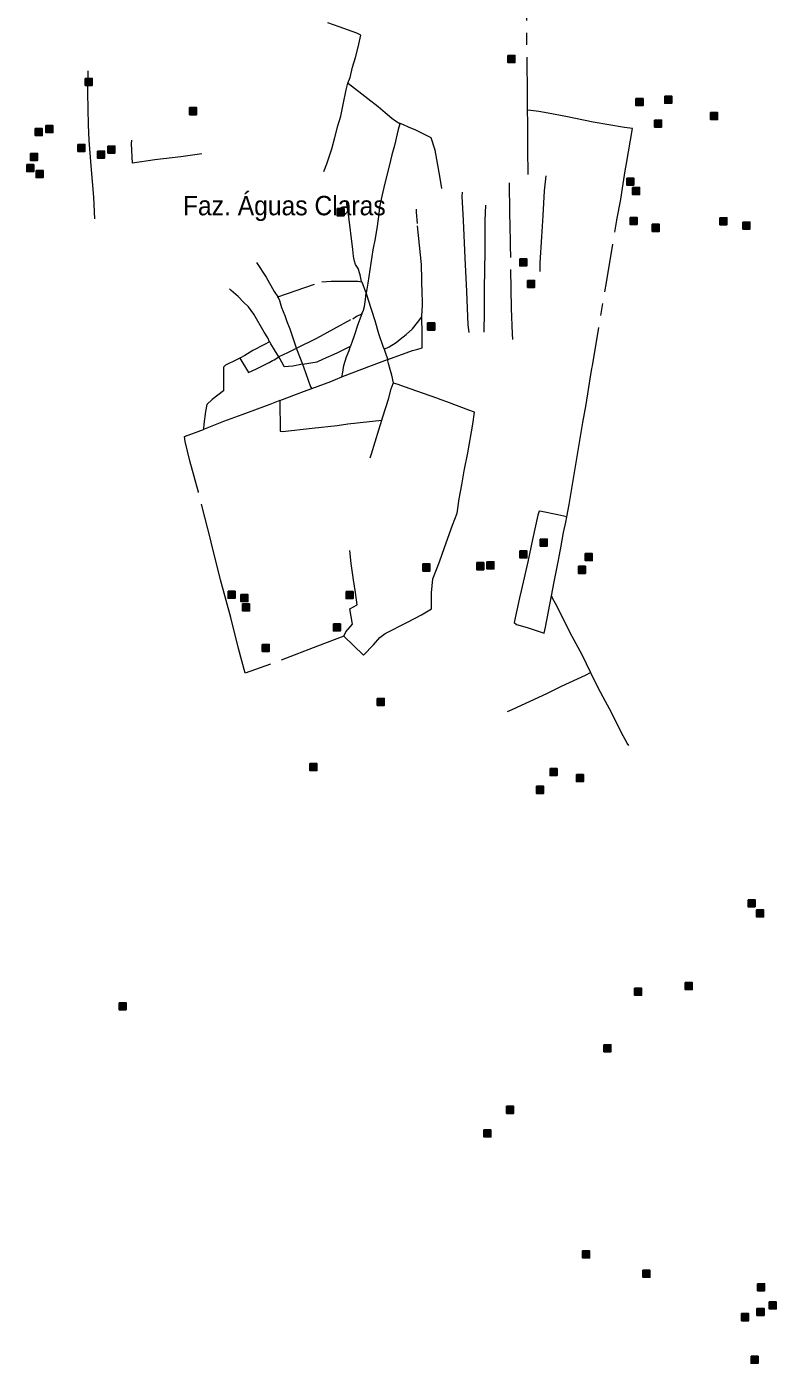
# Model space of a CAD drawing. Extents: x 393.5 to 446.9, y 8064.8 to 8120.4.
# Drawn here: x 432.73 to 438.91, y 8065.16 to 8076.18 of the extents above; entities that cross this region are included whole.
import ezdxf

# ---------------------------------------------------------------- set-up
doc = ezdxf.new("R2010")
doc.units = 0
doc.header["$LTSCALE"] = 0.064
doc.linetypes.add('DOT_DASHED', pattern=[7.7, 5, -1.2, 0.3, -1.2])
doc.layers.add('2', color=7, linetype='Continuous', lineweight=25)
doc.layers.add('22', color=7, linetype='DOT_DASHED', lineweight=13)
doc.layers.add('61', color=7, linetype='Continuous')

msp = doc.modelspace()

# ---------------------------------------------------------------- hatches: boundary and pattern name
at = {"layer": '2'}
for points in [[(436.7008, 8075.9394), (436.7588, 8075.9394), (436.7588, 8075.8814), (436.7008, 8075.8814)], [(433.2153, 8075.7507), (433.2733, 8075.7507), (433.2733, 8075.6927), (433.2153, 8075.6927)], [(434.0766, 8075.5093), (434.1346, 8075.5093), (434.1346, 8075.4513), (434.0766, 8075.4513)], [(437.757, 8075.584), (437.815, 8075.584), (437.815, 8075.526), (437.757, 8075.526)], [(437.9944, 8075.6043), (438.0524, 8075.6043), (438.0524, 8075.5463), (437.9944, 8075.5463)], [(437.9107, 8075.4072), (437.9687, 8075.4072), (437.9687, 8075.3492), (437.9107, 8075.3492)], [(438.3714, 8075.4688), (438.4294, 8075.4688), (438.4294, 8075.4108), (438.3714, 8075.4108)], [(432.8034, 8075.3368), (432.8614, 8075.3368), (432.8614, 8075.2788), (432.8034, 8075.2788)], [(432.8914, 8075.3612), (432.9494, 8075.3612), (432.9494, 8075.3032), (432.8914, 8075.3032)], [(433.1555, 8075.2066), (433.2135, 8075.2066), (433.2135, 8075.1486), (433.1555, 8075.1486)], [(433.4027, 8075.1932), (433.4607, 8075.1932), (433.4607, 8075.1352), (433.4027, 8075.1352)], [(432.7644, 8075.1322), (432.8224, 8075.1322), (432.8224, 8075.0742), (432.7644, 8075.0742)], [(433.3169, 8075.1513), (433.3749, 8075.1513), (433.3749, 8075.0933), (433.3169, 8075.0933)], [(432.7334, 8075.0405), (432.7914, 8075.0405), (432.7914, 8074.9825), (432.7334, 8074.9825)], [(432.8107, 8074.9915), (432.8687, 8074.9915), (432.8687, 8074.9335), (432.8107, 8074.9335)], [(437.6806, 8074.9289), (437.7386, 8074.9289), (437.7386, 8074.8709), (437.6806, 8074.8709)], [(437.7293, 8074.8512), (437.7873, 8074.8512), (437.7873, 8074.7932), (437.7293, 8074.7932)], [(435.2927, 8074.6769), (435.3507, 8074.6769), (435.3507, 8074.6189), (435.2927, 8074.6189)], [(437.7087, 8074.6045), (437.7667, 8074.6045), (437.7667, 8074.5465), (437.7087, 8074.5465)], [(437.8905, 8074.5475), (437.9485, 8074.5475), (437.9485, 8074.4895), (437.8905, 8074.4895)], [(438.4494, 8074.6018), (438.5074, 8074.6018), (438.5074, 8074.5438), (438.4494, 8074.5438)], [(438.6388, 8074.566), (438.6968, 8074.566), (438.6968, 8074.508), (438.6388, 8074.508)], [(436.7982, 8074.2633), (436.8562, 8074.2633), (436.8562, 8074.2053), (436.7982, 8074.2053)], [(436.8634, 8074.0856), (436.9214, 8074.0856), (436.9214, 8074.0276), (436.8634, 8074.0276)], [(436.0393, 8073.7341), (436.0973, 8073.7341), (436.0973, 8073.6761), (436.0393, 8073.6761)], [(436.9673, 8071.9524), (437.0253, 8071.9524), (437.0253, 8071.8944), (436.9673, 8071.8944)], [(436.4436, 8071.7582), (436.5016, 8071.7582), (436.5016, 8071.7002), (436.4436, 8071.7002)], [(436.5274, 8071.765), (436.5854, 8071.765), (436.5854, 8071.707), (436.5274, 8071.707)], [(436.8, 8071.8555), (436.858, 8071.8555), (436.858, 8071.7975), (436.8, 8071.7975)], [(437.3382, 8071.833), (437.3962, 8071.833), (437.3962, 8071.775), (437.3382, 8071.775)], [(435.9995, 8071.7473), (436.0575, 8071.7473), (436.0575, 8071.6893), (435.9995, 8071.6893)], [(437.2825, 8071.7281), (437.3405, 8071.7281), (437.3405, 8071.6701), (437.2825, 8071.6701)], [(434.3936, 8071.5231), (434.4516, 8071.5231), (434.4516, 8071.4651), (434.3936, 8071.4651)], [(434.4991, 8071.4956), (434.5571, 8071.4956), (434.5571, 8071.4376), (434.4991, 8071.4376)], [(434.5131, 8071.4187), (434.5711, 8071.4187), (434.5711, 8071.3607), (434.5131, 8071.3607)], [(435.3668, 8071.5196), (435.4248, 8071.5196), (435.4248, 8071.4616), (435.3668, 8071.4616)], [(435.2622, 8071.2538), (435.3202, 8071.2538), (435.3202, 8071.1958), (435.2622, 8071.1958)], [(434.6747, 8071.084), (434.7327, 8071.084), (434.7327, 8071.026), (434.6747, 8071.026)], [(435.6233, 8070.6386), (435.6813, 8070.6386), (435.6813, 8070.5806), (435.6233, 8070.5806)], [(435.0681, 8070.1018), (435.1261, 8070.1018), (435.1261, 8070.0438), (435.0681, 8070.0438)], [(437.0482, 8070.0603), (437.1062, 8070.0603), (437.1062, 8070.0023), (437.0482, 8070.0023)], [(437.2652, 8070.0107), (437.3232, 8070.0107), (437.3232, 8069.9527), (437.2652, 8069.9527)], [(436.9366, 8069.9142), (436.9946, 8069.9142), (436.9946, 8069.8562), (436.9366, 8069.8562)], [(438.6814, 8068.9791), (438.7394, 8068.9791), (438.7394, 8068.9211), (438.6814, 8068.9211)], [(438.7515, 8068.895), (438.8095, 8068.895), (438.8095, 8068.837), (438.7515, 8068.837)], [(437.7456, 8068.2495), (437.8036, 8068.2495), (437.8036, 8068.1915), (437.7456, 8068.1915)], [(438.1629, 8068.2961), (438.2209, 8068.2961), (438.2209, 8068.2381), (438.1629, 8068.2381)], [(433.4945, 8068.1298), (433.5525, 8068.1298), (433.5525, 8068.0718), (433.4945, 8068.0718)], [(437.4928, 8067.7838), (437.5508, 8067.7838), (437.5508, 8067.7258), (437.4928, 8067.7258)], [(436.69, 8067.276), (436.748, 8067.276), (436.748, 8067.218), (436.69, 8067.218)], [(436.5033, 8067.0814), (436.5613, 8067.0814), (436.5613, 8067.0234), (436.5033, 8067.0234)], [(437.3165, 8066.0846), (437.3745, 8066.0846), (437.3745, 8066.0266), (437.3165, 8066.0266)], [(437.8144, 8065.9249), (437.8724, 8065.9249), (437.8724, 8065.8669), (437.8144, 8065.8669)], [(438.7597, 8065.8136), (438.8177, 8065.8136), (438.8177, 8065.7556), (438.7597, 8065.7556)], [(438.7546, 8065.6103), (438.8126, 8065.6103), (438.8126, 8065.5523), (438.7546, 8065.5523)], [(438.8557, 8065.6639), (438.9137, 8065.6639), (438.9137, 8065.6059), (438.8557, 8065.6059)], [(438.6279, 8065.5669), (438.6859, 8065.5669), (438.6859, 8065.5089), (438.6279, 8065.5089)], [(438.7061, 8065.2157), (438.7641, 8065.2157), (438.7641, 8065.1577), (438.7061, 8065.1577)]]:
    msp.add_hatch(color=256, dxfattribs=at).paths.add_polyline_path(points)

# ---------------------------------------------------------------- linework, layer by layer
for points in [[(436.7008, 8075.9394), (436.7588, 8075.9394), (436.7588, 8075.8814), (436.7008, 8075.8814)], [(433.2153, 8075.7507), (433.2733, 8075.7507), (433.2733, 8075.6927), (433.2153, 8075.6927)], [(434.0766, 8075.5093), (434.1346, 8075.5093), (434.1346, 8075.4513), (434.0766, 8075.4513)], [(437.757, 8075.584), (437.815, 8075.584), (437.815, 8075.526), (437.757, 8075.526)], [(437.9944, 8075.6043), (438.0524, 8075.6043), (438.0524, 8075.5463), (437.9944, 8075.5463)], [(437.9107, 8075.4072), (437.9687, 8075.4072), (437.9687, 8075.3492), (437.9107, 8075.3492)], [(438.3714, 8075.4688), (438.4294, 8075.4688), (438.4294, 8075.4108), (438.3714, 8075.4108)], [(432.8034, 8075.3368), (432.8614, 8075.3368), (432.8614, 8075.2788), (432.8034, 8075.2788)], [(432.8914, 8075.3612), (432.9494, 8075.3612), (432.9494, 8075.3032), (432.8914, 8075.3032)], [(433.1555, 8075.2066), (433.2135, 8075.2066), (433.2135, 8075.1486), (433.1555, 8075.1486)], [(433.4027, 8075.1932), (433.4607, 8075.1932), (433.4607, 8075.1352), (433.4027, 8075.1352)], [(432.7644, 8075.1322), (432.8224, 8075.1322), (432.8224, 8075.0742), (432.7644, 8075.0742)], [(433.3169, 8075.1513), (433.3749, 8075.1513), (433.3749, 8075.0933), (433.3169, 8075.0933)], [(432.7334, 8075.0405), (432.7914, 8075.0405), (432.7914, 8074.9825), (432.7334, 8074.9825)], [(432.8107, 8074.9915), (432.8687, 8074.9915), (432.8687, 8074.9335), (432.8107, 8074.9335)], [(437.6806, 8074.9289), (437.7386, 8074.9289), (437.7386, 8074.8709), (437.6806, 8074.8709)], [(437.7293, 8074.8512), (437.7873, 8074.8512), (437.7873, 8074.7932), (437.7293, 8074.7932)], [(435.2927, 8074.6769), (435.3507, 8074.6769), (435.3507, 8074.6189), (435.2927, 8074.6189)], [(437.7087, 8074.6045), (437.7667, 8074.6045), (437.7667, 8074.5465), (437.7087, 8074.5465)], [(437.8905, 8074.5475), (437.9485, 8074.5475), (437.9485, 8074.4895), (437.8905, 8074.4895)], [(438.4494, 8074.6018), (438.5074, 8074.6018), (438.5074, 8074.5438), (438.4494, 8074.5438)], [(438.6388, 8074.566), (438.6968, 8074.566), (438.6968, 8074.508), (438.6388, 8074.508)], [(436.7982, 8074.2633), (436.8562, 8074.2633), (436.8562, 8074.2053), (436.7982, 8074.2053)], [(436.8634, 8074.0856), (436.9214, 8074.0856), (436.9214, 8074.0276), (436.8634, 8074.0276)], [(436.0393, 8073.7341), (436.0973, 8073.7341), (436.0973, 8073.6761), (436.0393, 8073.6761)], [(436.9673, 8071.9524), (437.0253, 8071.9524), (437.0253, 8071.8944), (436.9673, 8071.8944)], [(436.4436, 8071.7582), (436.5016, 8071.7582), (436.5016, 8071.7002), (436.4436, 8071.7002)], [(436.5274, 8071.765), (436.5854, 8071.765), (436.5854, 8071.707), (436.5274, 8071.707)], [(436.8, 8071.8555), (436.858, 8071.8555), (436.858, 8071.7975), (436.8, 8071.7975)], [(437.3382, 8071.833), (437.3962, 8071.833), (437.3962, 8071.775), (437.3382, 8071.775)], [(435.9995, 8071.7473), (436.0575, 8071.7473), (436.0575, 8071.6893), (435.9995, 8071.6893)], [(437.2825, 8071.7281), (437.3405, 8071.7281), (437.3405, 8071.6701), (437.2825, 8071.6701)], [(434.3936, 8071.5231), (434.4516, 8071.5231), (434.4516, 8071.4651), (434.3936, 8071.4651)], [(434.4991, 8071.4956), (434.5571, 8071.4956), (434.5571, 8071.4376), (434.4991, 8071.4376)], [(434.5131, 8071.4187), (434.5711, 8071.4187), (434.5711, 8071.3607), (434.5131, 8071.3607)], [(435.3668, 8071.5196), (435.4248, 8071.5196), (435.4248, 8071.4616), (435.3668, 8071.4616)], [(435.2622, 8071.2538), (435.3202, 8071.2538), (435.3202, 8071.1958), (435.2622, 8071.1958)], [(434.6747, 8071.084), (434.7327, 8071.084), (434.7327, 8071.026), (434.6747, 8071.026)], [(435.6233, 8070.6386), (435.6813, 8070.6386), (435.6813, 8070.5806), (435.6233, 8070.5806)], [(435.0681, 8070.1018), (435.1261, 8070.1018), (435.1261, 8070.0438), (435.0681, 8070.0438)], [(437.0482, 8070.0603), (437.1062, 8070.0603), (437.1062, 8070.0023), (437.0482, 8070.0023)], [(437.2652, 8070.0107), (437.3232, 8070.0107), (437.3232, 8069.9527), (437.2652, 8069.9527)], [(436.9366, 8069.9142), (436.9946, 8069.9142), (436.9946, 8069.8562), (436.9366, 8069.8562)], [(438.6814, 8068.9791), (438.7394, 8068.9791), (438.7394, 8068.9211), (438.6814, 8068.9211)], [(438.7515, 8068.895), (438.8095, 8068.895), (438.8095, 8068.837), (438.7515, 8068.837)], [(437.7456, 8068.2495), (437.8036, 8068.2495), (437.8036, 8068.1915), (437.7456, 8068.1915)], [(438.1629, 8068.2961), (438.2209, 8068.2961), (438.2209, 8068.2381), (438.1629, 8068.2381)], [(433.4945, 8068.1298), (433.5525, 8068.1298), (433.5525, 8068.0718), (433.4945, 8068.0718)], [(437.4928, 8067.7838), (437.5508, 8067.7838), (437.5508, 8067.7258), (437.4928, 8067.7258)], [(436.69, 8067.276), (436.748, 8067.276), (436.748, 8067.218), (436.69, 8067.218)], [(436.5033, 8067.0814), (436.5613, 8067.0814), (436.5613, 8067.0234), (436.5033, 8067.0234)], [(437.3165, 8066.0846), (437.3745, 8066.0846), (437.3745, 8066.0266), (437.3165, 8066.0266)], [(437.8144, 8065.9249), (437.8724, 8065.9249), (437.8724, 8065.8669), (437.8144, 8065.8669)], [(438.7597, 8065.8136), (438.8177, 8065.8136), (438.8177, 8065.7556), (438.7597, 8065.7556)], [(438.7546, 8065.6103), (438.8126, 8065.6103), (438.8126, 8065.5523), (438.7546, 8065.5523)], [(438.8557, 8065.6639), (438.9137, 8065.6639), (438.9137, 8065.6059), (438.8557, 8065.6059)], [(438.6279, 8065.5669), (438.6859, 8065.5669), (438.6859, 8065.5089), (438.6279, 8065.5089)], [(438.7061, 8065.2157), (438.7641, 8065.2157), (438.7641, 8065.1577), (438.7061, 8065.1577)]]:
    msp.add_lwpolyline(points, close=True, dxfattribs=at)
at = {"layer": '22'}
for p, q in [((435.3309, 8073.2902), (435.337, 8073.2925)), ((437.0598, 8071.4844), (437.0667, 8071.4669)), ((435.3482, 8071.1532), (435.3472, 8071.152)), ((435.3482, 8071.1532), (435.3488, 8071.1526))]:
    msp.add_line(p, q, dxfattribs=at)
for points in [[(436.8631, 8075.4892), (436.8618, 8075.6067), (436.8564, 8076.2406), (436.8543, 8076.3126), (436.8533, 8076.5596), (436.8501, 8076.6423)], [(435.3823, 8075.7101), (435.3999, 8075.758), (435.4184, 8075.8436), (435.4434, 8075.9228), (435.4658, 8076.0084), (435.4882, 8076.1068), (435.4552, 8076.1234), (435.3091, 8076.1745), (435.2156, 8076.2077)], [(433.296, 8074.593), (433.2857, 8074.7718), (433.265, 8075.029), (433.2485, 8075.2426), (433.2423, 8075.3672), (433.2381, 8075.6324), (433.2402, 8075.8132)], [(435.1835, 8074.9827), (435.2069, 8075.0463), (435.248, 8075.1696), (435.2742, 8075.2639), (435.2985, 8075.3583), (435.3228, 8075.4381), (435.3424, 8075.5351), (435.3686, 8075.6566), (435.3823, 8075.7101)], [(435.3823, 8075.7101), (435.3852, 8075.7077), (435.5457, 8075.5856), (435.63, 8075.5179), (435.6893, 8075.4706), (435.7446, 8075.4233), (435.7749, 8075.4016), (435.8104, 8075.3798)], [(437.6367, 8074.79), (437.6401, 8074.8101), (437.6682, 8074.989), (437.6796, 8075.0486), (437.7275, 8075.338), (437.6635, 8075.3455), (437.4042, 8075.391), (437.1798, 8075.4364), (437.033, 8075.4637), (436.9564, 8075.4773), (436.8908, 8075.4864), (436.8631, 8075.4892)], [(436.868, 8074.9581), (436.8645, 8075.1669), (436.8642, 8075.3851), (436.8631, 8075.4879), (436.8631, 8075.4892)], [(435.8104, 8075.3798), (435.8102, 8075.379), (435.8095, 8075.3764), (435.7959, 8075.3287), (435.7669, 8075.1984), (435.7439, 8075.1198), (435.7215, 8075.0265), (435.6866, 8074.8879), (435.6616, 8074.7806), (435.6425, 8074.6931), (435.6373, 8074.633), (435.6222, 8074.5327), (435.6064, 8074.4318), (435.5879, 8074.3372), (435.546, 8074.0611), (435.5385, 8074.014), (435.5328, 8073.9831), (435.5326, 8073.9819)], [(436.155, 8074.8423), (436.139, 8074.9435), (436.1002, 8075.1587), (436.0692, 8075.2602), (435.9415, 8075.3228), (435.8809, 8075.3484), (435.8349, 8075.3714), (435.8115, 8075.3794), (435.8104, 8075.3798)], [(434.1769, 8075.1274), (434.0035, 8075.1043), (433.7904, 8075.078), (433.6059, 8075.0518), (433.5964, 8075.2108), (433.6012, 8075.2416)], [(436.966, 8074.1597), (436.967, 8074.2301), (436.981, 8074.4453), (436.9904, 8074.6196), (437.0021, 8074.8249), (437.0177, 8074.9462)], [(436.7175, 8074.6102), (436.7164, 8074.6424), (436.7143, 8074.8906)], [(435.4288, 8074.2851), (435.4221, 8074.3399), (435.3863, 8074.6308), (435.3736, 8074.7096), (435.372, 8074.7435)], [(436.3828, 8073.6547), (436.3734, 8073.719), (436.3625, 8073.9948), (436.3492, 8074.2699), (436.3344, 8074.5784), (436.3242, 8074.7791), (436.3258, 8074.814)], [(437.3975, 8073.3808), (437.5141, 8074.0677), (437.6003, 8074.5835), (437.6319, 8074.7526), (437.6322, 8074.754), (437.6367, 8074.79)], [(435.9968, 8073.9269), (435.9939, 8073.9654), (435.9872, 8074.2163), (435.9543, 8074.5555), (435.9478, 8074.6468), (435.9464, 8074.6722)], [(436.5054, 8073.6591), (436.5085, 8073.827), (436.5085, 8074.0165), (436.514, 8074.3249), (436.5147, 8074.5787), (436.5186, 8074.7052)], [(436.7426, 8073.5972), (436.7395, 8073.6449), (436.73, 8073.8542), (436.7233, 8074.3726), (436.7186, 8074.5666), (436.7175, 8074.6102)], [(435.4949, 8074.0758), (435.4825, 8074.1314), (435.465, 8074.1824), (435.4443, 8074.2165), (435.4347, 8074.2443), (435.4299, 8074.269), (435.4288, 8074.2851)], [(434.6285, 8074.2339), (434.7065, 8074.1112), (434.775, 8073.9927), (434.8025, 8073.951), (434.8034, 8073.9496)], [(434.8034, 8073.9496), (435.166, 8074.0742), (435.2425, 8074.0792), (435.3459, 8074.0792), (435.4637, 8074.0776), (435.4952, 8074.0744)], [(435.4952, 8074.0743), (435.4952, 8074.0744), (435.4949, 8074.0758)], [(435.4952, 8074.0743), (435.5267, 8073.9922), (435.5326, 8073.9819)], [(434.7359, 8073.5786), (434.7211, 8073.6122), (434.6904, 8073.6576), (434.6049, 8073.8065), (434.5629, 8073.8676), (434.5209, 8073.9068), (434.4757, 8073.9522), (434.4192, 8074.0023), (434.4047, 8074.0164)], [(435.4952, 8073.8085), (435.5114, 8073.8397), (435.5184, 8073.8696), (435.5279, 8073.928), (435.5324, 8073.9793), (435.5326, 8073.9819)], [(435.5326, 8073.9819), (435.5329, 8073.9806), (435.5332, 8073.9797)], [(435.5332, 8073.9797), (435.5456, 8073.9326), (435.6029, 8073.7535), (435.6346, 8073.6487), (435.6706, 8073.5439), (435.6795, 8073.5191)], [(434.9567, 8073.5276), (434.9503, 8073.5508), (434.9229, 8073.6341), (434.9052, 8073.6827), (434.881, 8073.7438), (434.8632, 8073.794), (434.8374, 8073.8598), (434.8196, 8073.9177), (434.8099, 8073.9412), (434.8034, 8073.9496)], [(435.9922, 8073.7855), (435.9922, 8073.7895), (435.9971, 8073.8824), (435.9968, 8073.9269)], [(434.9622, 8073.5294), (435.1266, 8073.6076), (435.4213, 8073.7697), (435.4526, 8073.7894)], [(435.4952, 8073.8084), (435.4626, 8073.7218), (435.434, 8073.6277), (435.4165, 8073.5813), (435.4022, 8073.5427)], [(435.4526, 8073.7894), (435.4559, 8073.7913), (435.4952, 8073.8085)], [(435.6795, 8073.5191), (435.7218, 8073.5382), (435.7783, 8073.5743), (435.8127, 8073.601), (435.8609, 8073.6384), (435.9146, 8073.6852), (435.956, 8073.7374), (435.9922, 8073.7855)], [(435.7096, 8073.4335), (435.9146, 8073.5061), (435.9573, 8073.5182), (435.9932, 8073.5288), (435.9932, 8073.605), (435.9934, 8073.6451), (435.9922, 8073.7855)], [(434.7347, 8073.578), (434.6946, 8073.557), (434.5991, 8073.5061), (434.5307, 8073.4659), (434.4898, 8073.4445), (434.4893, 8073.4443)], [(434.8123, 8073.4551), (434.7757, 8073.5122), (434.7471, 8073.5616), (434.7366, 8073.5776), (434.7359, 8073.5786), (434.7347, 8073.578)], [(434.9576, 8073.5248), (434.938, 8073.5169), (434.8839, 8073.4875), (434.8123, 8073.4551)], [(434.9567, 8073.5276), (434.9598, 8073.5286), (434.9615, 8073.5291), (434.9622, 8073.5294)], [(434.9567, 8073.5276), (434.9571, 8073.5262), (434.9576, 8073.5248)], [(434.9576, 8073.5248), (434.9585, 8073.522), (435.008, 8073.3949)], [(435.008, 8073.3949), (435.1269, 8073.4146), (435.1794, 8073.4378), (435.2924, 8073.4872), (435.3984, 8073.5408), (435.4022, 8073.5427)], [(435.3309, 8073.2902), (435.3357, 8073.3118), (435.3484, 8073.3828), (435.3707, 8073.4538), (435.391, 8073.5072), (435.4019, 8073.5418), (435.4022, 8073.5427)], [(435.6795, 8073.5191), (435.6979, 8073.4675), (435.7096, 8073.4335)], [(434.4893, 8073.4443), (434.4472, 8073.4221), (434.3894, 8073.3947)], [(434.4893, 8073.4443), (434.4898, 8073.4435), (434.5626, 8073.3258), (434.6278, 8073.3552), (434.6832, 8073.3834)], [(434.6832, 8073.3834), (434.7328, 8073.4093), (434.7602, 8073.4237), (434.7741, 8073.4304), (434.8108, 8073.4541), (434.8123, 8073.4551)], [(435.008, 8073.3949), (434.9286, 8073.3783), (434.857, 8073.3721), (434.8489, 8073.3912), (434.8123, 8073.4551)], [(435.337, 8073.2925), (435.5774, 8073.383), (435.7076, 8073.4327), (435.7088, 8073.4332), (435.7096, 8073.4335)], [(435.731, 8073.3501), (435.7152, 8073.399), (435.7107, 8073.4209), (435.7096, 8073.4335)], [(434.3894, 8073.3947), (434.3724, 8073.3866), (434.3549, 8073.3696), (434.3565, 8073.1735), (434.2634, 8073.1032), (434.2188, 8073.0616), (434.2077, 8073.0044), (434.195, 8072.901), (434.1912, 8072.8612), (434.1905, 8072.8586), (434.1896, 8072.8554)], [(435.008, 8073.3949), (435.0082, 8073.3944), (435.0082, 8073.3943), (435.0084, 8073.3935), (435.0085, 8073.3932), (435.0092, 8073.3905), (435.0103, 8073.3865)], [(435.0103, 8073.3865), (435.0144, 8073.3717), (435.0733, 8073.2086), (435.0829, 8073.1932)], [(435.7563, 8073.2394), (435.7425, 8073.304), (435.731, 8073.3501)], [(437.1867, 8072.1347), (437.2054, 8072.2366), (437.2445, 8072.4685), (437.2843, 8072.6981), (437.3194, 8072.9125), (437.3452, 8073.0618), (437.3796, 8073.274), (437.3936, 8073.3589), (437.3975, 8073.3808)], [(434.8207, 8073.0945), (434.9572, 8073.1468), (435.016, 8073.1685), (435.0829, 8073.1932)], [(435.0829, 8073.1932), (435.2402, 8073.2516), (435.28, 8073.267), (435.3303, 8073.2899), (435.3309, 8073.2902)], [(435.6626, 8072.9327), (435.6674, 8072.9521), (435.6945, 8073.0386), (435.7152, 8073.105), (435.7374, 8073.1914), (435.7548, 8073.2358), (435.7558, 8073.2382), (435.7563, 8073.2394)], [(436.1515, 8073.1002), (436.1144, 8073.1139), (435.9488, 8073.173), (435.8485, 8073.2086), (435.796, 8073.2271), (435.7567, 8073.2393), (435.7563, 8073.2394)], [(434.8207, 8073.0945), (434.7371, 8073.0614), (434.5064, 8072.9764), (434.3553, 8072.9209), (434.1919, 8072.8562), (434.1896, 8072.8554)], [(434.8207, 8073.0945), (434.8218, 8072.8432), (434.8425, 8072.8401), (435.0859, 8072.8663), (435.2928, 8072.8895), (435.38, 8072.9015), (435.661, 8072.9325), (435.6626, 8072.9327)], [(435.3488, 8071.1526), (435.5098, 8070.9942), (435.5926, 8071.0806), (435.6451, 8071.1408), (435.6896, 8071.1748), (435.8733, 8071.2681), (435.9879, 8071.3283), (436.0706, 8071.3762), (436.0706, 8071.5105), (436.081, 8071.6255), (436.1367, 8071.766), (436.1773, 8071.8825), (436.2441, 8072.0678), (436.2815, 8072.1674), (436.299, 8072.2832), (436.3197, 8072.4005), (436.3412, 8072.514), (436.3714, 8072.6623), (436.412, 8072.9008), (436.4263, 8072.9996), (436.3786, 8073.0166), (436.198, 8073.0838), (436.1515, 8073.1002)], [(435.3472, 8071.152), (435.3468, 8071.1516), (435.1308, 8071.0694), (434.7424, 8070.9211), (434.5355, 8070.8478), (434.4801, 8071.0496), (434.4175, 8071.3072), (434.3321, 8071.6155), (434.2542, 8071.93), (434.1491, 8072.3401), (434.0774, 8072.5969), (434.0408, 8072.7574), (434.0345, 8072.7976), (434.1474, 8072.8392), (434.1896, 8072.8554)], [(435.5656, 8072.6224), (435.5767, 8072.6548), (435.6356, 8072.854), (435.6626, 8072.9327)], [(437.1867, 8072.1347), (437.1125, 8072.1534), (436.978, 8072.1803), (436.9599, 8072.1816), (436.9489, 8072.1493), (436.9031, 8071.9502), (436.8664, 8071.765), (436.8109, 8071.5255), (436.7963, 8071.4682), (436.7533, 8071.265), (436.7713, 8071.2489), (436.8601, 8071.2233), (436.9988, 8071.1762), (437.0098, 8071.2274), (437.0598, 8071.4844)], [(437.0598, 8071.4844), (437.0835, 8071.5994), (437.0974, 8071.6694), (437.1168, 8071.7797), (437.1306, 8071.8524), (437.138, 8071.8809), (437.1583, 8072.0077), (437.1783, 8072.0907), (437.1867, 8072.1347)], [(435.3482, 8071.1532), (435.3653, 8071.187), (435.4194, 8071.2518), (435.3972, 8071.3769), (435.4592, 8071.4093), (435.4433, 8071.5127), (435.4282, 8071.6154), (435.4092, 8071.7508), (435.3964, 8071.8588)], [(437.0667, 8071.4669), (437.0917, 8071.4238), (437.1575, 8071.294), (437.2116, 8071.1823), (437.3114, 8071.0007), (437.3814, 8070.8534)], [(437.0263, 8070.6826), (437.1428, 8070.7391), (437.3398, 8070.832), (437.3814, 8070.8534)], [(437.5375, 8070.5527), (437.5069, 8070.6146), (437.4438, 8070.727), (437.4105, 8070.801), (437.382, 8070.8523), (437.3814, 8070.8534)], [(436.6976, 8070.5305), (436.7365, 8070.548), (437.0263, 8070.6826)], [(437.6983, 8070.2513), (437.6831, 8070.2687), (437.6512, 8070.3306), (437.5375, 8070.5527)]]:
    msp.add_lwpolyline(points, dxfattribs=at)

# ---------------------------------------------------------------- texts
at = {"layer": '61', "width": 0.95}
msp.add_text('Faz. Águas Claras', height=0.16, dxfattribs=at).set_placement((434.0212, 8074.622))

doc.saveas('drawing.dxf')
